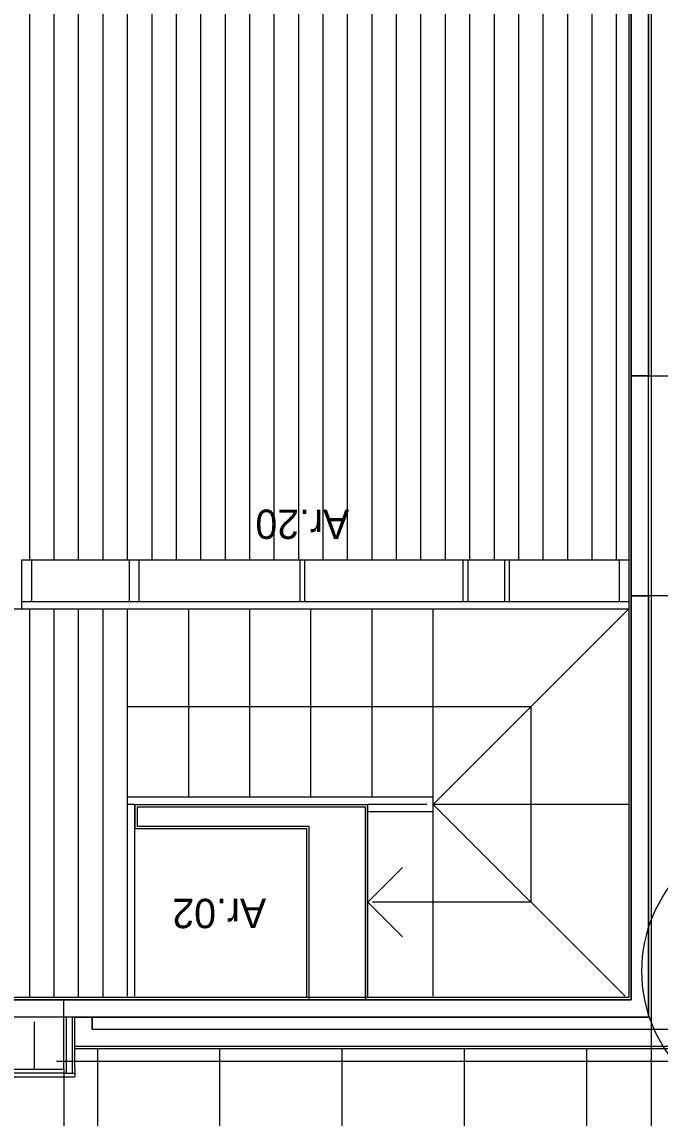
# Model space of a CAD drawing. Extents: x 1248 to 1356, y -443 to -224.
# Drawn here: x 1326.71 to 1329.32, y -238.907 to -234.424 of the extents above; entities that cross this region are included whole.
import ezdxf

# ---------------------------------------------------------------- set-up
doc = ezdxf.new("R2010")
doc.units = 0
for name, color, linetype in [('corte', 7, 'Continuous'), ('estereoctomias', 7, 'Continuous'), ('ind-pormenores', 7, 'Continuous'), ('Level 1', 7, 'Continuous'), ('Level 10', 7, 'Continuous'), ('Level 13', 7, 'Continuous'), ('Level 2', 7, 'Continuous'), ('Level 4', 7, 'Continuous'), ('Level 40', 7, 'Continuous'), ('revestimentos', 7, 'Continuous'), ('vermelhos-cont', 7, 'Continuous')]:
    doc.layers.add(name, color=color, linetype=linetype)

msp = doc.modelspace()

# ---------------------------------------------------------------- linework, layer by layer
at = {"layer": 'corte'}
for p, q in [((1329.2018, -238.424), (1329.2018, -232.264)), ((1329.2718, -236.7713), (1329.2718, -232.264)), ((1329.2718, -238.494), (1329.2718, -236.7713)), ((1329.2018, -238.424), (1326.0168, -238.424)), ((1326.9968, -238.494), (1329.2718, -238.494)), ((1326.9968, -238.544), (1330.4325, -238.544)), ((1330.5225, -238.614), (1326.9268, -238.614))]:
    msp.add_line(p, q, dxfattribs=at)
msp.add_lwpolyline([(1329.2018, -235.8713), (1329.4318, -235.8713), (1329.4318, -236.7713), (1329.2018, -236.7713)], close=True, dxfattribs=at)
at = {"layer": 'estereoctomias'}
for points in [[(1329.2718, -232.264), (1329.2718, -235.8713), (1329.2018, -235.8713), (1329.2018, -232.264)], [(1329.2718, -236.7713), (1329.2718, -238.494), (1326.0868, -238.494), (1326.0868, -238.709), (1326.0168, -238.709), (1326.0168, -238.424), (1329.2018, -238.424), (1329.2018, -236.7713)], [(1327.1818, -237.634), (1328.1143, -237.634), (1328.1143, -238.424), (1327.8843, -238.424), (1327.8843, -237.714), (1327.1818, -237.714)], [(1330.5225, -238.424), (1330.5225, -238.614), (1326.9268, -238.614), (1326.9268, -238.494), (1326.9968, -238.494), (1326.9968, -238.544), (1330.4875, -238.544), (1330.4875, -238.424)]]:
    msp.add_lwpolyline(points, close=True, dxfattribs=at)
at = {"layer": 'ind-pormenores'}
msp.add_circle((1329.8293, -238.3059), 0.5842, dxfattribs=at)
at = {"layer": 'Level 1'}
for p, q in [((1329.2018, -232.264), (1329.2018, -238.424)), ((1327.1818, -237.634), (1328.1143, -237.634)), ((1327.1818, -237.714), (1327.1818, -237.634)), ((1328.1143, -238.424), (1328.1143, -237.634)), ((1327.8843, -237.714), (1327.1818, -237.714)), ((1327.8843, -238.424), (1327.8843, -237.714)), ((1326.9268, -238.494), (1326.0868, -238.494)), ((1326.9268, -238.614), (1326.9268, -238.494)), ((1326.9968, -238.544), (1326.9968, -238.494))]:
    msp.add_line(p, q, dxfattribs=at)
at = {"layer": 'Level 10'}
for p, q in [((1326.7418, -236.624), (1326.7418, -232.274)), ((1326.8418, -236.624), (1326.8418, -232.274)), ((1326.9418, -236.624), (1326.9418, -232.274)), ((1327.0418, -236.624), (1327.0418, -232.274)), ((1327.1418, -236.624), (1327.1418, -232.274)), ((1327.2418, -236.624), (1327.2418, -232.274)), ((1327.3418, -236.624), (1327.3418, -232.274)), ((1327.4418, -236.624), (1327.4418, -232.274)), ((1327.5418, -236.624), (1327.5418, -232.274)), ((1327.6418, -236.624), (1327.6418, -232.274)), ((1327.7418, -236.624), (1327.7418, -232.274)), ((1327.8418, -236.624), (1327.8418, -232.274)), ((1327.9418, -236.624), (1327.9418, -232.274)), ((1328.0418, -236.624), (1328.0418, -232.274)), ((1328.1418, -236.624), (1328.1418, -232.274)), ((1328.2418, -236.624), (1328.2418, -232.274)), ((1328.3418, -236.624), (1328.3418, -232.274)), ((1328.4418, -236.624), (1328.4418, -232.274)), ((1328.5418, -236.624), (1328.5418, -232.274)), ((1328.6418, -236.624), (1328.6418, -232.274)), ((1328.7418, -236.624), (1328.7418, -232.274)), ((1328.8418, -236.624), (1328.8418, -232.274)), ((1328.9418, -236.624), (1328.9418, -232.274)), ((1329.0418, -236.624), (1329.0418, -232.274)), ((1329.1418, -236.624), (1329.1418, -232.274)), ((1326.7418, -238.414), (1326.7418, -236.824)), ((1326.8418, -238.414), (1326.8418, -236.824)), ((1326.9418, -238.414), (1326.9418, -236.824)), ((1327.0418, -238.414), (1327.0418, -236.824)), ((1327.0183, -238.624), (1327.0183, -240.224)), ((1327.5183, -238.624), (1327.5183, -240.224)), ((1328.0183, -238.624), (1328.0183, -240.224)), ((1328.5183, -238.624), (1328.5183, -240.224)), ((1329.0183, -238.624), (1329.0183, -240.224)), ((1326.8518, -238.674), (1330.4725, -238.674))]:
    msp.add_line(p, q, dxfattribs=at)
at = {"layer": 'Level 13'}
for p, q in [((1326.7098, -236.824), (1326.7098, -236.624)), ((1326.7098, -236.624), (1329.1918, -236.624)), ((1326.7498, -236.794), (1326.7498, -236.624)), ((1327.1498, -236.794), (1327.1498, -236.624)), ((1327.1898, -236.794), (1327.1898, -236.624)), ((1327.8471, -236.794), (1327.8471, -236.624)), ((1327.8671, -236.794), (1327.8671, -236.624)), ((1328.5144, -236.794), (1328.5144, -236.624)), ((1328.5344, -236.794), (1328.5344, -236.624)), ((1328.6844, -236.794), (1328.6844, -236.624)), ((1328.7044, -236.794), (1328.7044, -236.624)), ((1329.1518, -236.624), (1329.1518, -236.794)), ((1326.7098, -236.794), (1329.1918, -236.794)), ((1326.7098, -236.824), (1329.1918, -236.824)), ((1326.7098, -236.824), (1329.1918, -236.824)), ((1326.7098, -236.824), (1329.1918, -236.824)), ((1327.1383, -236.824), (1329.1918, -236.824)), ((1327.1418, -238.409), (1327.1418, -237.624)), ((1327.1718, -237.624), (1327.1418, -237.624)), ((1327.1718, -238.409), (1327.1718, -237.624)), ((1326.8818, -238.709), (1326.8818, -238.494)), ((1326.8918, -238.724), (1326.8918, -238.494)), ((1326.9168, -238.724), (1326.9168, -238.494)), ((1326.9268, -238.704), (1326.9268, -238.614)), ((1326.8818, -238.709), (1325.9768, -238.709)), ((1326.8818, -238.709), (1326.8818, -238.724)), ((1326.9268, -238.704), (1326.9268, -238.724)), ((1326.8818, -238.724), (1326.0168, -238.724)), ((1326.8818, -238.724), (1326.0168, -238.724)), ((1326.8818, -238.724), (1326.0268, -238.724)), ((1326.8818, -238.724), (1326.8818, -238.739)), ((1326.8818, -238.724), (1326.9268, -238.724)), ((1326.8818, -238.739), (1326.9268, -238.739)), ((1326.9268, -238.724), (1326.9268, -238.739))]:
    msp.add_line(p, q, dxfattribs=at)
at = {"layer": 'Level 2'}
for p, q in [((1327.1418, -237.624), (1327.1418, -236.824)), ((1327.1418, -237.624), (1327.1418, -236.824)), ((1327.3918, -237.594), (1327.3918, -236.824)), ((1327.6418, -237.594), (1327.6418, -236.824)), ((1327.8918, -237.594), (1327.8918, -236.824)), ((1328.1418, -237.594), (1328.1418, -236.824)), ((1328.3918, -237.594), (1328.3918, -236.824)), ((1328.3918, -237.624), (1329.1918, -236.824)), ((1327.1418, -237.224), (1328.7918, -237.224)), ((1328.7918, -238.024), (1328.7918, -237.224)), ((1328.3918, -237.594), (1327.1418, -237.594)), ((1328.3918, -237.654), (1328.3918, -237.594)), ((1328.3659, -237.624), (1328.1243, -237.624)), ((1329.1918, -237.624), (1328.3918, -237.624)), ((1328.3918, -237.624), (1329.1768, -238.409)), ((1328.3918, -237.654), (1328.1243, -237.654)), ((1328.3918, -238.409), (1328.3918, -237.654)), ((1328.2657, -237.8826), (1328.1243, -238.024)), ((1328.2657, -238.1654), (1328.1243, -238.024)), ((1328.7918, -238.024), (1328.1433, -238.024))]:
    msp.add_line(p, q, dxfattribs=at)
at = {"layer": 'Level 4'}
for p, q in [((1325.8918, -236.824), (1326.7098, -236.824)), ((1326.8818, -238.494), (1326.8818, -238.424)), ((1326.7593, -238.514), (1326.7593, -238.709)), ((1325.1968, -238.739), (1326.8818, -238.739)), ((1326.8818, -238.724), (1326.8818, -239.5941))]:
    msp.add_line(p, q, dxfattribs=at)
msp.add_ellipse((1326.8818, -238.739), major_axis=(-0.8551, 0), ratio=0.999998, start_param=0, end_param=1.570796, dxfattribs=at)
at = {"layer": 'revestimentos'}
for p, q in [((1329.1918, -232.274), (1329.1918, -238.414)), ((1327.1718, -237.624), (1328.1243, -237.624)), ((1327.1718, -237.624), (1327.1718, -237.724)), ((1328.1243, -238.414), (1328.1243, -237.624)), ((1327.8743, -237.724), (1327.1718, -237.724)), ((1327.8743, -238.414), (1327.8743, -237.724)), ((1329.1918, -238.414), (1326.0368, -238.414)), ((1329.1918, -238.414), (1328.1243, -238.414)), ((1330.5125, -238.624), (1326.9268, -238.624))]:
    msp.add_line(p, q, dxfattribs=at)
at = {"layer": 'vermelhos-cont'}
msp.add_line((1329.284, -250.7923), (1329.284, -229.6198), dxfattribs=at)

# ---------------------------------------------------------------- texts
at = {"layer": 'Level 40'}
for s, p in [('Ar.20', (1328.0482, -236.4183)), ('Ar.02', (1327.7085, -238.0102))]:
    msp.add_text(s, height=0.12, rotation=180, dxfattribs=at).set_placement(p)

doc.saveas('drawing.dxf')
